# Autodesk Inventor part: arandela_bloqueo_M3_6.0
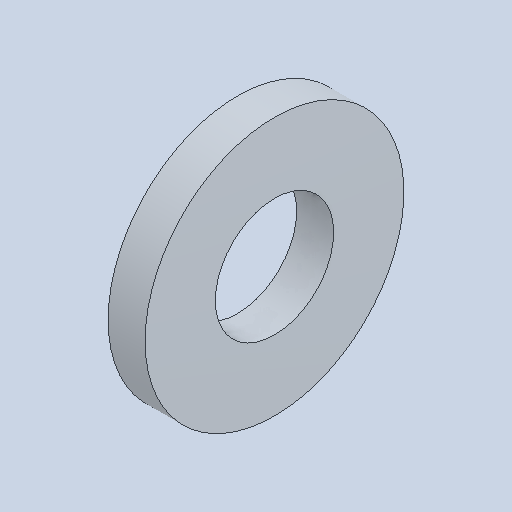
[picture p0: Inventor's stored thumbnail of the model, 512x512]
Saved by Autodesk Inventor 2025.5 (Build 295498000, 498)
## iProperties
Created: 2026-10
Part Number: arandela_bloqueo_M3_6.0
Material: Genérico
Document SubType Name: Modeling
Designer: Luis M
Density: 1 g/cm^3
Appearance: Valor por defecto
Author: Luis M
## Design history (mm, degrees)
feature "Base1"
node "Sólido1"
